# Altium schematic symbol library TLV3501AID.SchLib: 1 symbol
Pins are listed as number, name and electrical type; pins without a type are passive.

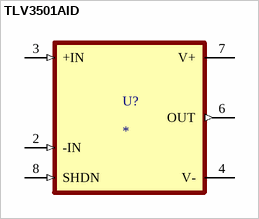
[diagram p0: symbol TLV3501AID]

## TLV3501AID
designator U?
MP: TLV3501AID
footprint TLV3501AID
pins: 2 -IN (in), 3 +IN (in), 4 V- (power), 6 OUT (out), 7 V+ (power), 8 SHDN (in)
